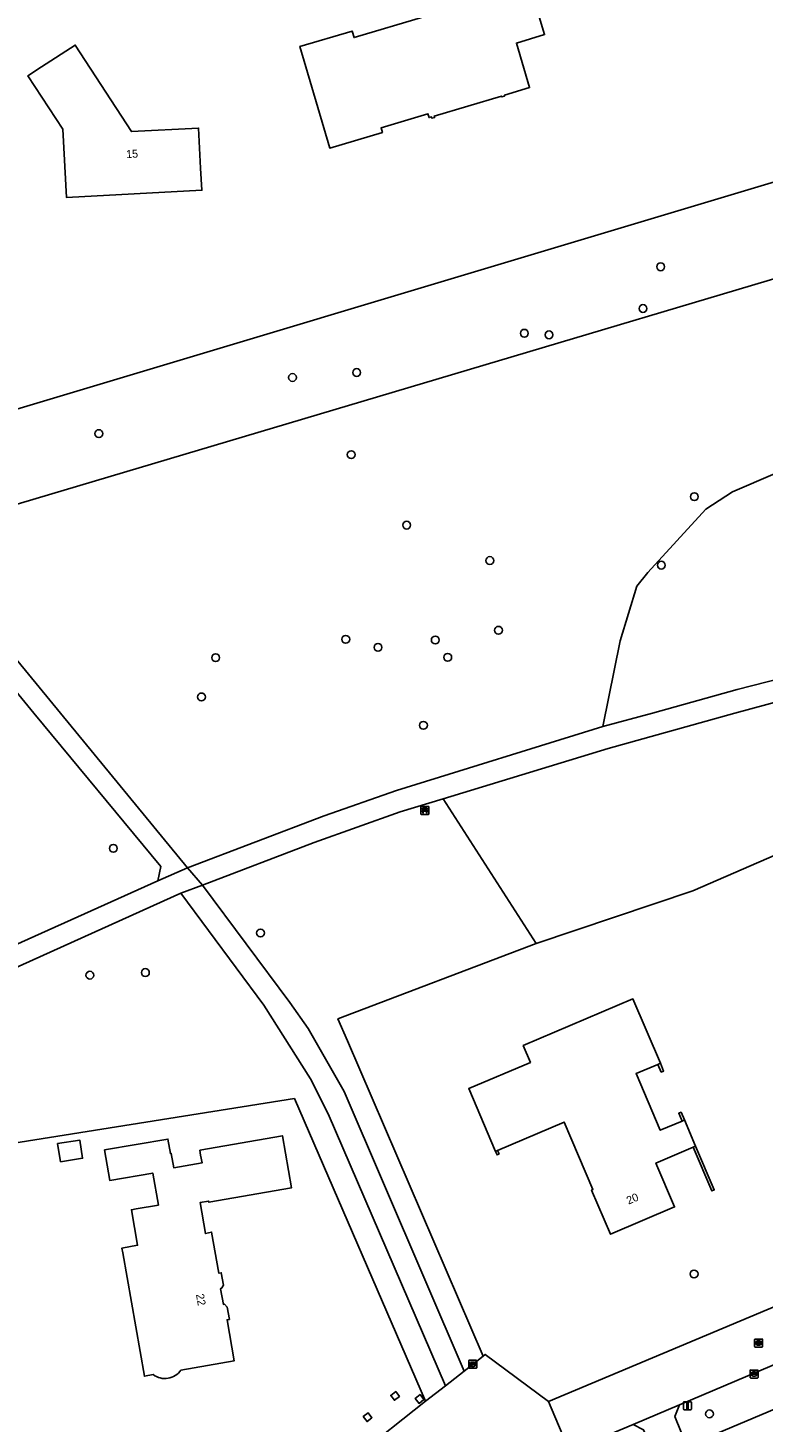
# Model space of a CAD drawing. Extents: x 162417 to 163722, y 384268 to 385417.
# Drawn here: x 163118.6 to 163210.5, y 384911.4 to 385085.6 of the extents above; entities that cross this region are included whole.
import ezdxf

# ---------------------------------------------------------------- set-up
doc = ezdxf.new("R2010")
doc.units = 0
for name, color, linetype in [('IMGEO_Bank', 7, 'Continuous'), ('IMGEO_Boom', 7, 'Continuous'), ('IMGEO_Erf', 7, 'Continuous'), ('IMGEO_Gemengd_bos', 7, 'Continuous'), ('IMGEO_Groenvoorziening', 7, 'Continuous'), ('IMGEO_Kolk', 7, 'Continuous'), ('IMGEO_Lichtmast', 7, 'Continuous'), ('IMGEO_Loofbos', 7, 'Continuous'), ('IMGEO_Muur', 7, 'Continuous'), ('IMGEO_Pand', 7, 'Continuous'), ('IMGEO_Pand_nummerreeks', 7, 'Continuous'), ('IMGEO_Pand_vergunning_verleend', 7, 'Continuous'), ('IMGEO_Rijbaan_lokaal_gesloten', 7, 'Continuous'), ('IMGEO_Rioolput', 7, 'Continuous'), ('IMGEO_Voetpad_halfverhard', 7, 'Continuous'), ('IMGEO_Voetpad_open', 7, 'Continuous')]:
    doc.layers.add(name, color=color, linetype=linetype)

msp = doc.modelspace()

# ---------------------------------------------------------------- linework, layer by layer
at = {"layer": 'IMGEO_Bank'}
for p, q in [((163167.7, 384987.41), (163167.7, 384988.25)), ((163167.7, 384988.25), (163167.7, 384987.41)), ((163167.78, 384988.34), (163168.62, 384988.34)), ((163168.62, 384988.34), (163167.78, 384988.34)), ((163168.01, 384987.85), (163168.01, 384987.95)), ((163168.34, 384987.96), (163168.06, 384987.96)), ((163168.06, 384987.95), (163168.06, 384987.85)), ((163168.06, 384987.84), (163168.34, 384987.84)), ((163168.35, 384987.85), (163168.35, 384987.95)), ((163168.39, 384987.95), (163168.39, 384987.85)), ((163168.7, 384988.26), (163168.7, 384987.42)), ((163168.7, 384987.42), (163168.7, 384988.26)), ((163168.63, 384987.34), (163167.79, 384987.34)), ((163167.79, 384987.34), (163168.63, 384987.34)), ((163168.4, 384987.74), (163168.01, 384987.74))]:
    msp.add_line(p, q, dxfattribs=at)
for points in [[(163167.95, 384987.74), (163167.81, 384987.74), (163167.92, 384987.84), (163168.01, 384987.84)], [(163168.01, 384987.96), (163167.92, 384987.96), (163167.92, 384988.12), (163168.48, 384988.12), (163168.48, 384987.96), (163168.4, 384987.96)], [(163168.4, 384987.84), (163168.48, 384987.84), (163168.6, 384987.74), (163168.46, 384987.74)], [(163168, 384987.73), (163168, 384987.52), (163167.96, 384987.52), (163167.96, 384987.73)], [(163168.45, 384987.73), (163168.45, 384987.52), (163168.41, 384987.52), (163168.41, 384987.73)]]:
    msp.add_lwpolyline(points, dxfattribs=at)
for centre, radius, start, end in [((163167.78, 384988.26), 0.0779, 92.4484, 184.2845), ((163167.78, 384988.26), 0.0779, 92.4484, 184.2845), ((163168.01, 384987.95), 0.00671, 2.8957, 87.1043), ((163168.01, 384987.85), 0.00671, 272.8957, 357.1043), ((163168.06, 384987.95), 0.00671, 92.8957, 177.1043), ((163168.06, 384987.85), 0.00671, 182.8957, 267.1043), ((163168.34, 384987.95), 0.00671, 2.8957, 87.1043), ((163168.34, 384987.85), 0.00671, 272.8957, 357.1043), ((163168.4, 384987.95), 0.00671, 92.8957, 177.1043), ((163168.4, 384987.85), 0.00671, 182.8957, 267.1043), ((163168.63, 384988.26), 0.0779, 2.4484, 94.2845), ((163168.63, 384988.26), 0.0779, 2.4484, 94.2845), ((163167.78, 384987.42), 0.0779, 182.4484, 274.2845), ((163167.78, 384987.42), 0.0779, 182.4484, 274.2845), ((163167.95, 384987.73), 0.00671, 2.8957, 87.1043), ((163168.01, 384987.73), 0.00671, 92.8957, 177.1043), ((163168.4, 384987.73), 0.00671, 2.8957, 87.1043), ((163168.46, 384987.73), 0.00671, 92.8957, 177.1043), ((163168.63, 384987.42), 0.0779, 272.4484, 4.2845), ((163168.63, 384987.42), 0.0779, 272.4484, 4.2845)]:
    msp.add_arc(centre, radius, start, end, dxfattribs=at)
at = {"layer": 'IMGEO_Boom'}
for centre in [(163197.68, 385055.79), (163195.47, 385050.57), (163180.64, 385047.48), (163183.72, 385047.28), (163151.65, 385041.95), (163159.68, 385042.57), (163127.44, 385034.94), (163158.99, 385032.31), (163201.89, 385027.05), (163165.93, 385023.5), (163176.32, 385019.07), (163197.76, 385018.49), (163177.4, 385010.36), (163158.31, 385009.23), (163169.5, 385009.14), (163142.05, 385006.93), (163162.34, 385008.22), (163171.06, 385006.98), (163140.27, 385002.03), (163168.02, 384998.48), (163129.25, 384983.1), (163147.65, 384972.53), (163126.32, 384967.25), (163133.26, 384967.58), (163201.86, 384929.91), (163203.78, 384912.43)]:
    msp.add_circle(centre, 0.489, dxfattribs=at)
at = {"layer": 'IMGEO_Erf'}
for points in [[(163180.88, 385092.47), (163183.16, 385084.8), (163179.64, 385083.75), (163181.3, 385078.18), (163178.14, 385077.23), (163178.17, 385077.12), (163177.83, 385077.02), (163177.8, 385077.13), (163169.38, 385074.63), (163169.43, 385074.46), (163169.08, 385074.36), (163169.04, 385074.52), (163168.73, 385074.43), (163168.58, 385074.91), (163162.72, 385073.16), (163162.89, 385072.59), (163156.31, 385070.62), (163152.58, 385083.32), (163159.11, 385085.24), (163159.36, 385084.43), (163168.09, 385087.01)], [(163109.64, 385035.76), (163200.68, 385063.02), (163281.97, 385087.41)], [(163134.24, 384917.33), (163133.14, 384917.12), (163130.43, 384932.54), (163130.32, 384933.15), (163132.29, 384933.5), (163131.51, 384937.93), (163132.11, 384938.04), (163134.89, 384938.53), (163134.18, 384942.53), (163128.8, 384941.61), (163128.15, 384945.42), (163136.08, 384946.78), (163136.39, 384944.96), (163136.49, 384944.98), (163136.8, 384943.19), (163140.34, 384943.79), (163140.17, 384944.78), (163140.07, 384945.37), (163150.39, 384947.19), (163151.53, 384940.69), (163141.21, 384938.87), (163141.17, 384939.03), (163140.11, 384938.85), (163140.76, 384934.95), (163141.54, 384935.14), (163142.45, 384930.01), (163142.74, 384930.06), (163143.02, 384928.53), (163142.83, 384928.17), (163142.66, 384928.06), (163143.01, 384926.11), (163143.16, 384926.14), (163143.49, 384925.78), (163143.77, 384924.23), (163143.48, 384924.2), (163144.36, 384919.07), (163137.7, 384917.91)]]:
    msp.add_lwpolyline(points, dxfattribs=at)
for points in [[(163124.48, 385083.5), (163131.52, 385072.68), (163139.91, 385073.12), (163140.17, 385068.13), (163140.32, 385065.36), (163123.38, 385064.46), (163122.93, 385072.99), (163118.58, 385079.67), (163120.29, 385080.78)], [(163318.55, 385000), (163308.97, 385023.36), (163277.36, 385010.29), (163269.66, 385007.07), (163253.07, 385000), (163231.53, 384990.76), (163201.72, 384977.8), (163182.1, 384971.2), (163157.34, 384961.78), (163158.51, 384959.07), (163175.47, 384919.62), (163175.76, 384919.85), (163183.67, 384913.96), (163328.96, 384974.96)], [(163204.37, 384940.42), (163204.07, 384940.29), (163201.74, 384945.76), (163197.08, 384943.78), (163199.42, 384938.29), (163191.39, 384934.87), (163189.04, 384940.39), (163189.22, 384940.47), (163185.63, 384948.9), (163177.28, 384945.34), (163177.47, 384944.91), (163177.22, 384944.8), (163177.03, 384945.23), (163173.69, 384953.08), (163181.4, 384956.36), (163180.51, 384958.45), (163194.21, 384964.29), (163197.64, 384956.24), (163198.05, 384955.27), (163197.75, 384955.15), (163197.34, 384956.11), (163194.61, 384954.95), (163197.62, 384947.87), (163200.35, 384949.03), (163199.94, 384950), (163200.23, 384950.12), (163200.64, 384949.16), (163202.04, 384945.89)], [(163159.56, 384907.09), (163168.29, 384914), (163151.9, 384951.84), (163097.15, 384943.13), (163103.62, 384899.24), (163109.03, 384862.7), (163116.8, 384810.17), (163172.67, 384818.52)], [(163165.02, 384914.6), (163164.55, 384915.21), (163163.93, 384914.74), (163164.4, 384914.13)], [(163163.93, 384914.74), (163164.55, 384915.21), (163165.02, 384914.6), (163164.4, 384914.13)], [(163168.09, 384914.23), (163167.6, 384914.84), (163166.99, 384914.36), (163167.47, 384913.74)], [(163166.99, 384914.36), (163167.6, 384914.84), (163168.09, 384914.23), (163167.47, 384913.74)], [(163161.58, 384911.94), (163161.1, 384912.56), (163160.49, 384912.08), (163160.97, 384911.47)], [(163160.49, 384912.08), (163161.1, 384912.56), (163161.58, 384911.94), (163160.97, 384911.47)]]:
    msp.add_lwpolyline(points, close=True, dxfattribs=at)
msp.add_arc((163135.7, 384919.24), 2.4, 232.4077, 326.3293, dxfattribs=at)
at = {"layer": 'IMGEO_Gemengd_bos'}
for points in [[(163104.31, 385022.27), (163286.02, 385076.36), (163281.97, 385087.41), (163200.68, 385063.02), (163109.64, 385035.76), (163096.43, 385031.75)], [(163253.07, 385000), (163269.66, 385007.07), (163277.36, 385010.29), (163264.45, 385019.53), (163236.32, 385008.78), (163225.93, 385005.28), (163221.42, 385003.91), (163206.97, 385000), (163191.13, 384995.57), (163170.48, 384989.3), (163182.1, 384971.2), (163201.72, 384977.8), (163231.53, 384990.76)], [(163182.1, 384971.2), (163170.48, 384989.3), (163165.11, 384987.68), (163154.34, 384983.85), (163140.38, 384978.5), (163151.33, 384963.85), (163153.6, 384960.57), (163158.12, 384952.7), (163173.11, 384917.78), (163175.47, 384919.62), (163158.51, 384959.07), (163157.34, 384961.78)]]:
    msp.add_lwpolyline(points, close=True, dxfattribs=at)
at = {"layer": 'IMGEO_Groenvoorziening'}
for points in [[(163286.02, 385076.36), (163104.31, 385022.27), (163122.66, 385000), (163138.54, 384980.68), (163155.6, 384987.18), (163164.64, 384990.34), (163190.46, 384998.35), (163192.6, 385009.04), (163194.69, 385015.88), (163196.06, 385017.57), (163203.31, 385025.48), (163206.68, 385027.67), (163212, 385029.94), (163221.1, 385031.58), (163228.41, 385031.37), (163249.98, 385025.8), (163256.09, 385024.66), (163270.81, 385024.87), (163306.47, 385038.41), (163291.63, 385064.16)], [(163110.23, 384967.99), (163134.8, 384979.05), (163135.19, 384980.85), (163119.33, 385000), (163094.01, 385030.86)]]:
    msp.add_lwpolyline(points, dxfattribs=at)
for points in [[(163196.67, 385000), (163207.26, 385002.94), (163220.47, 385006.34), (163231.85, 385010.07), (163270.81, 385024.87), (163256.09, 385024.66), (163249.98, 385025.8), (163228.41, 385031.37), (163221.1, 385031.58), (163212, 385029.94), (163206.68, 385027.67), (163203.31, 385025.48), (163196.06, 385017.57), (163194.69, 385015.88), (163192.6, 385009.04), (163190.46, 384998.35)], [(163200.97, 384908.41), (163226.91, 384919.36), (163225.35, 384923.27), (163224.3, 384923.83), (163200.02, 384913.55), (163199.45, 384912.09)]]:
    msp.add_lwpolyline(points, close=True, dxfattribs=at)
at = {"layer": 'IMGEO_Kolk'}
for p, q in [((163173.69, 384918.2), (163173.69, 384919.05)), ((163173.76, 384919.13), (163174.62, 384919.13)), ((163173.95, 384918.62), (163173.95, 384918.63)), ((163173.99, 384918.67), (163174.39, 384918.67)), ((163174.39, 384918.58), (163173.99, 384918.58)), ((163174.18, 384918.91), (163174.2, 384918.91)), ((163174.2, 384918.35), (163174.18, 384918.35)), ((163174.43, 384918.63), (163174.43, 384918.62)), ((163174.69, 384919.05), (163174.69, 384918.2)), ((163174.62, 384918.13), (163173.76, 384918.13)), ((163208.86, 384916.99), (163208.86, 384917.84)), ((163208.94, 384917.91), (163209.79, 384917.91)), ((163209.79, 384916.91), (163208.94, 384916.91)), ((163209.12, 384917.41), (163209.12, 384917.42)), ((163209.16, 384917.46), (163209.56, 384917.46)), ((163209.56, 384917.37), (163209.16, 384917.37)), ((163209.35, 384917.69), (163209.38, 384917.69)), ((163209.37, 384917.13), (163209.35, 384917.13)), ((163209.61, 384917.42), (163209.61, 384917.41)), ((163209.86, 384917.84), (163209.86, 384916.99))]:
    msp.add_line(p, q, dxfattribs=at)
for points in [[(163173.69, 384918.2), (163173.69, 384919.05)], [(163173.76, 384919.13), (163174.62, 384919.13)], [(163174.69, 384919.05), (163174.69, 384918.2)], [(163174.62, 384918.13), (163173.76, 384918.13)], [(163208.86, 384916.99), (163208.86, 384917.84)], [(163208.94, 384917.91), (163209.79, 384917.91)], [(163209.79, 384916.91), (163208.94, 384916.91)], [(163209.86, 384917.84), (163209.86, 384916.99)]]:
    msp.add_lwpolyline(points, dxfattribs=at)
for centre, radius, start, end in [((163173.77, 384919.05), 0.0765, 91.552, 178.448), ((163173.77, 384919.05), 0.0765, 91.552, 178.448), ((163173.77, 384918.2), 0.0765, 181.552, 268.448), ((163173.77, 384918.2), 0.0765, 181.552, 268.448), ((163173.99, 384918.63), 0.0403, 85.8775, 175.7526), ((163173.99, 384918.62), 0.0366, 178.938, 274.7102), ((163174.39, 384918.63), 0.0386, 1.7309, 96.639), ((163174.39, 384918.63), 0.043, 264.8664, 352.4533), ((163174.61, 384919.05), 0.0765, 1.552, 88.448), ((163174.61, 384919.05), 0.0765, 1.552, 88.448), ((163174.61, 384918.2), 0.0765, 271.552, 358.448), ((163174.61, 384918.2), 0.0765, 271.552, 358.448), ((163208.94, 384917.84), 0.0765, 91.552, 178.448), ((163208.94, 384917.84), 0.0765, 91.552, 178.448), ((163208.94, 384916.99), 0.0765, 181.552, 268.448), ((163208.94, 384916.99), 0.0765, 181.552, 268.448), ((163209.16, 384917.42), 0.0403, 85.8775, 175.7526), ((163209.16, 384917.41), 0.0366, 178.938, 274.7102), ((163209.57, 384917.42), 0.0386, 1.7309, 96.639), ((163209.56, 384917.41), 0.043, 264.8664, 352.4533), ((163209.79, 384917.84), 0.0765, 1.552, 88.448), ((163209.79, 384917.84), 0.0765, 1.552, 88.448), ((163209.79, 384916.99), 0.0765, 271.552, 358.448), ((163209.79, 384916.99), 0.0765, 271.552, 358.448)]:
    msp.add_arc(centre, radius, start, end, dxfattribs=at)
for centre, major_axis, ratio, start_param, end_param in [((163174.18, 384918.63), (-0.387, 0.002), 0.722429, 4.712389, 7.853982), ((163174.2, 384918.63), (-0.39, 0.002), 0.717154, 1.570796, 4.712389), ((163209.35, 384917.41), (-0.387, 0.002), 0.722429, 4.712389, 7.853982), ((163209.37, 384917.41), (-0.39, 0.002), 0.717154, 1.570796, 4.712389)]:
    msp.add_ellipse(centre, major_axis=major_axis, ratio=ratio, start_param=start_param, end_param=end_param, dxfattribs=at)
at = {"layer": 'IMGEO_Lichtmast'}
for p, q in [((163200.54, 384913.05), (163200.54, 384913.85)), ((163200.54, 384913.85), (163200.54, 384913.05)), ((163200.64, 384913.95), (163201.42, 384913.95)), ((163201.42, 384913.95), (163200.64, 384913.95)), ((163201.42, 384912.95), (163200.64, 384912.95)), ((163200.64, 384912.95), (163201.42, 384912.95)), ((163201.52, 384913.85), (163201.52, 384913.05)), ((163201.52, 384913.05), (163201.52, 384913.85))]:
    msp.add_line(p, q, dxfattribs=at)
msp.add_lwpolyline([(163200.96, 384913.82), (163201.11, 384913.82), (163201.11, 384913.07), (163200.96, 384913.07), (163200.96, 384913.82)], dxfattribs=at)
for centre, start, end in [((163200.64, 384913.85), 90, 180), ((163200.64, 384913.85), 90, 180), ((163200.64, 384913.05), 180, 270), ((163200.64, 384913.05), 180, 270), ((163201.42, 384913.85), 0, 90), ((163201.42, 384913.85), 360, 90), ((163201.42, 384913.05), 270, 0), ((163201.42, 384913.05), 270, 0)]:
    msp.add_arc(centre, 0.1, start, end, dxfattribs=at)
at = {"layer": 'IMGEO_Loofbos'}
msp.add_lwpolyline([(163097.15, 384943.13), (163151.9, 384951.84), (163168.29, 384914), (163170.76, 384915.95), (163156.09, 384949.92), (163153.91, 384954.28), (163148.07, 384963.52), (163137.67, 384977.49), (163065.94, 384945.15)], dxfattribs=at)
at = {"layer": 'IMGEO_Muur'}
for points in [[(163197.64, 384956.24), (163197.34, 384956.11), (163197.75, 384955.15), (163198.05, 384955.27)], [(163200.35, 384949.03), (163200.64, 384949.16), (163200.23, 384950.12), (163199.94, 384950)], [(163177.28, 384945.34), (163177.03, 384945.23), (163177.22, 384944.8), (163177.47, 384944.91)], [(163202.04, 384945.89), (163201.74, 384945.76), (163204.07, 384940.29), (163204.37, 384940.42)]]:
    msp.add_lwpolyline(points, close=True, dxfattribs=at)
at = {"layer": 'IMGEO_Pand'}
for points in [[(163168.09, 385087.01), (163159.36, 385084.43), (163159.11, 385085.24), (163152.58, 385083.32), (163156.31, 385070.62), (163162.89, 385072.59), (163162.72, 385073.16), (163168.58, 385074.91), (163168.73, 385074.43), (163169.04, 385074.52), (163169.08, 385074.36), (163169.43, 385074.46), (163169.38, 385074.63), (163177.8, 385077.13), (163177.83, 385077.02), (163178.17, 385077.12), (163178.14, 385077.23), (163181.3, 385078.18), (163179.64, 385083.75), (163183.16, 385084.8), (163180.88, 385092.47)], [(163141.54, 384935.14), (163140.76, 384934.95), (163140.11, 384938.85), (163141.17, 384939.03), (163141.21, 384938.87), (163151.53, 384940.69), (163150.39, 384947.19), (163140.07, 384945.37), (163140.17, 384944.78), (163140.34, 384943.79), (163136.8, 384943.19), (163136.49, 384944.98), (163136.39, 384944.96), (163136.08, 384946.78), (163128.15, 384945.42), (163128.8, 384941.61), (163134.18, 384942.53), (163134.89, 384938.53), (163132.11, 384938.04), (163131.51, 384937.93), (163132.29, 384933.5), (163130.32, 384933.15), (163130.43, 384932.54), (163133.14, 384917.12), (163134.24, 384917.33)], [(163137.7, 384917.91), (163144.36, 384919.07), (163143.48, 384924.2), (163143.77, 384924.23), (163143.49, 384925.78), (163143.16, 384926.14), (163143.01, 384926.11), (163142.66, 384928.06), (163142.83, 384928.17), (163143.02, 384928.53), (163142.74, 384930.06), (163142.45, 384930.01), (163141.54, 384935.14)]]:
    msp.add_lwpolyline(points, dxfattribs=at)
for points in [[(163120.29, 385080.78), (163118.58, 385079.67), (163122.93, 385072.99), (163123.38, 385064.46), (163140.32, 385065.36), (163140.17, 385068.13), (163139.91, 385073.12), (163131.52, 385072.68), (163124.48, 385083.5)], [(163199.42, 384938.29), (163197.08, 384943.78), (163201.74, 384945.76), (163202.04, 384945.89), (163200.64, 384949.16), (163200.35, 384949.03), (163197.62, 384947.87), (163194.61, 384954.95), (163197.34, 384956.11), (163197.64, 384956.24), (163194.21, 384964.29), (163180.51, 384958.45), (163181.4, 384956.36), (163173.69, 384953.08), (163177.03, 384945.23), (163177.28, 384945.34), (163185.63, 384948.9), (163189.22, 384940.47), (163189.04, 384940.39), (163191.39, 384934.87)]]:
    msp.add_lwpolyline(points, close=True, dxfattribs=at)
msp.add_arc((163135.7, 384919.24), 2.4, 232.4077, 326.3293, dxfattribs=at)
at = {"layer": 'IMGEO_Pand_vergunning_verleend'}
msp.add_lwpolyline([(163122.29, 384946.2), (163125.05, 384946.64), (163125.41, 384944.37), (163122.66, 384943.93)], close=True, dxfattribs=at)
at = {"layer": 'IMGEO_Rijbaan_lokaal_gesloten'}
for points in [[(163337.56, 384978.79), (163336.54, 384978.15), (163336.2, 384978.01), (163333.91, 384977.04), (163328.96, 384974.96), (163183.67, 384913.96), (163186.27, 384907.76), (163194.23, 384911.1), (163200.02, 384913.55), (163224.3, 384923.83)], [(163186.27, 384907.76), (163183.67, 384913.96), (163175.76, 384919.85), (163175.47, 384919.62), (163173.11, 384917.78), (163170.76, 384915.95), (163168.29, 384914), (163159.56, 384907.09), (163172.67, 384818.52)]]:
    msp.add_lwpolyline(points, dxfattribs=at)
at = {"layer": 'IMGEO_Rioolput'}
for p, q in [((163209.42, 384920.86), (163209.42, 384921.71)), ((163209.49, 384921.78), (163210.34, 384921.78)), ((163210.42, 384921.71), (163210.42, 384920.86)), ((163210.34, 384920.78), (163209.49, 384920.78)), ((163209.67, 384921.28), (163209.67, 384921.29)), ((163210.11, 384921.24), (163209.71, 384921.24)), ((163209.72, 384921.33), (163210.11, 384921.33)), ((163209.9, 384921.56), (163209.93, 384921.56)), ((163209.93, 384921), (163209.9, 384921)), ((163210.16, 384921.29), (163210.16, 384921.28))]:
    msp.add_line(p, q, dxfattribs=at)
for points in [[(163209.42, 384920.86), (163209.42, 384921.71)], [(163209.49, 384921.78), (163210.34, 384921.78)], [(163210.42, 384921.71), (163210.42, 384920.86)], [(163210.34, 384920.78), (163209.49, 384920.78)]]:
    msp.add_lwpolyline(points, dxfattribs=at)
for centre, radius, start, end in [((163209.49, 384921.71), 0.0765, 91.552, 178.448), ((163209.49, 384921.71), 0.0765, 91.552, 178.448), ((163210.34, 384921.71), 0.0765, 1.552, 88.448), ((163210.34, 384921.71), 0.0765, 1.552, 88.448), ((163209.49, 384920.86), 0.0765, 181.552, 268.448), ((163209.49, 384920.86), 0.0765, 181.552, 268.448), ((163209.71, 384921.29), 0.0403, 85.8775, 175.7526), ((163209.71, 384921.28), 0.0366, 178.938, 274.7102), ((163210.12, 384921.29), 0.0386, 1.7309, 96.639), ((163210.12, 384921.28), 0.043, 264.8664, 352.4533), ((163210.34, 384920.86), 0.0765, 271.552, 358.448), ((163210.34, 384920.86), 0.0765, 271.552, 358.448)]:
    msp.add_arc(centre, radius, start, end, dxfattribs=at)
for centre, major_axis, ratio, start_param, end_param in [((163209.9, 384921.28), (-0.387, 0.002), 0.722429, 4.712389, 7.853982), ((163209.93, 384921.28), (-0.39, 0.002), 0.717154, 1.570796, 4.712389)]:
    msp.add_ellipse(centre, major_axis=major_axis, ratio=ratio, start_param=start_param, end_param=end_param, dxfattribs=at)
at = {"layer": 'IMGEO_Voetpad_halfverhard'}
for points in [[(163191.13, 384995.57), (163206.97, 385000), (163221.42, 385003.91), (163225.93, 385005.28), (163236.32, 385008.78), (163264.45, 385019.53), (163307.77, 385036.08), (163306.47, 385038.41), (163270.81, 385024.87), (163231.85, 385010.07), (163220.47, 385006.34), (163207.26, 385002.94), (163196.67, 385000), (163190.46, 384998.35), (163164.64, 384990.34), (163155.6, 384987.18), (163138.54, 384980.68), (163140.38, 384978.5), (163154.34, 384983.85), (163165.11, 384987.68), (163170.48, 384989.3)], [(163140.38, 384978.5), (163137.67, 384977.49), (163148.07, 384963.52), (163153.91, 384954.28), (163156.09, 384949.92), (163170.76, 384915.95), (163173.11, 384917.78), (163158.12, 384952.7), (163153.6, 384960.57), (163151.33, 384963.85)]]:
    msp.add_lwpolyline(points, close=True, dxfattribs=at)
for points in [[(163094.01, 385030.86), (163119.33, 385000), (163135.19, 384980.85), (163134.8, 384979.05), (163138.54, 384980.68), (163122.66, 385000), (163104.31, 385022.27)], [(163057.3, 384940.82), (163065.94, 384945.15), (163137.67, 384977.49), (163140.38, 384978.5), (163138.54, 384980.68), (163134.8, 384979.05), (163110.23, 384967.99), (163092.28, 384959.6), (163086.1, 384956.95), (163066.48, 384948.01), (163056.27, 384942.95), (163046.06, 384937.33), (163043.8, 384935.94), (163040.78, 384933.92), (163029.69, 384927.12)]]:
    msp.add_lwpolyline(points, dxfattribs=at)
at = {"layer": 'IMGEO_Voetpad_open'}
for points in [[(163202.03, 384905.85), (163227.94, 384916.77), (163226.91, 384919.36), (163200.97, 384908.41)], [(163200.97, 384908.41), (163199.45, 384912.09), (163200.02, 384913.55), (163194.23, 384911.1), (163195.54, 384910.44), (163197.08, 384906.76), (163198.14, 384904.21), (163202.03, 384905.85)]]:
    msp.add_lwpolyline(points, close=True, dxfattribs=at)

# ---------------------------------------------------------------- texts
at = {"layer": 'IMGEO_Pand_nummerreeks'}
for s, rotation, p in [('15', 3.0458, (163130.88, 385069.36)), ('20', 23.0616, (163193.66, 384938.57)), ('22', 279.9864, (163139.58, 384927.35))]:
    msp.add_text(s, height=1, rotation=rotation, dxfattribs=at).set_placement(p)

doc.saveas('drawing.dxf')
